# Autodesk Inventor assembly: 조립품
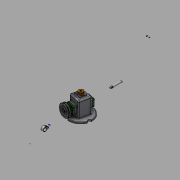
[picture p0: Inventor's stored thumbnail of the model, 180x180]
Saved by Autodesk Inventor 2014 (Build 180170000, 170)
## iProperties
Created: 2018-07
Part Number: 조립품
Document SubType Name: Assembly
Designer: user
Author: user
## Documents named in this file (16)
- C:\Users\user\Desktop\480708V1003\조립품.iam
- C:\Users\user\Desktop\480708V1003\V벨트풀리.ipt
- C:\Users\user\Desktop\480708V1003\고정핀 1.2x8.ipt
- C:\Users\user\Desktop\480708V1003\뒤커버.ipt
- C:\Users\user\Desktop\480708V1003\링크.ipt
- C:\Users\user\Desktop\480708V1003\멈춤나사 M3x8.ipt
- C:\Users\user\Desktop\480708V1003\베어링 12x32x10.ipt
- C:\Users\user\Desktop\480708V1003\본체.ipt
- C:\Users\user\Desktop\480708V1003\볼트 M4.ipt
- C:\Users\user\Desktop\480708V1003\부시.ipt
- C:\Users\user\Desktop\480708V1003\슬라이드.ipt
- C:\Users\user\Desktop\480708V1003\앞커버.ipt
- C:\Users\user\Desktop\480708V1003\오일 실 12 25 7.ipt
- C:\Users\user\Desktop\480708V1003\키 4x4x10.ipt
- C:\Users\user\Desktop\480708V1003\편심축.ipt
- C:\Users\user\Desktop\480708V1003\핀 5x18.ipt
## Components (3 placed, 3 different names)
1. V벨트풀리:1 — Mate:15, Flush:1, Mate:16
2. 고정핀 1.2x8:1
3. 핀 5x18:1
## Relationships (3: Mate 2, Flush 1)
- Mate:15: V벨트풀리:1
- Flush:1: V벨트풀리:1
- Mate:16: V벨트풀리:1
